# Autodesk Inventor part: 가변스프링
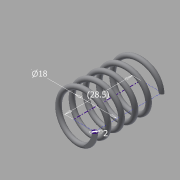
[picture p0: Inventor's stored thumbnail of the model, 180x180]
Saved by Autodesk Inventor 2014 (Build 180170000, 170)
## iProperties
Created: 2018-12
Part Number: 가변스프링
Material: Generic
Document SubType Name: Modeling
Designer: kh
Density: 1 g/cm^3
Appearance: Default
Author: kh
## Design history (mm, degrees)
sketch "스케치1"
  geometry: L1 (0, 0)-(9, 0); L2 (9, 0)-(9, 28.5); L3 (9, 28.5)-(0, 28.5); L4 (0, 28.5)-(0, 0); C1 r 1 at (9, 0)
  constraints: 8 end point, 2 parallel, 1 centre point, 1 coincident, 1 horizontal, 1 perpendicular
  dimensions: "d0" = 28.5 distance of L3.end L1.start (derived); "d1" = 18 diameter of L2 L4; "d3" = 2 diameter of C1
feature "코일2" sketch "스케치1" pitch "d12" = 10; turns "d14" = 5; dims "d13" = 28.5 (= d0), "d15" = 0, angle "d16" = 90 deg, angle "d17" = 90 deg, "d18" = 0, "d19" = 0
node "작업 평면1"
node "작업 평면2"
feature "분할1"
feature "분할2"
node "솔리드2"
